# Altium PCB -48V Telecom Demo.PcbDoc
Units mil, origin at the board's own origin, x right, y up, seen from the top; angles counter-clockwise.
Board outline 3540 x 2330 mil, 2 copper layers (Top Layer, Bottom Layer), stack 62 mil thick; 60 components, 18 nets, 123 pads, 37 vias.
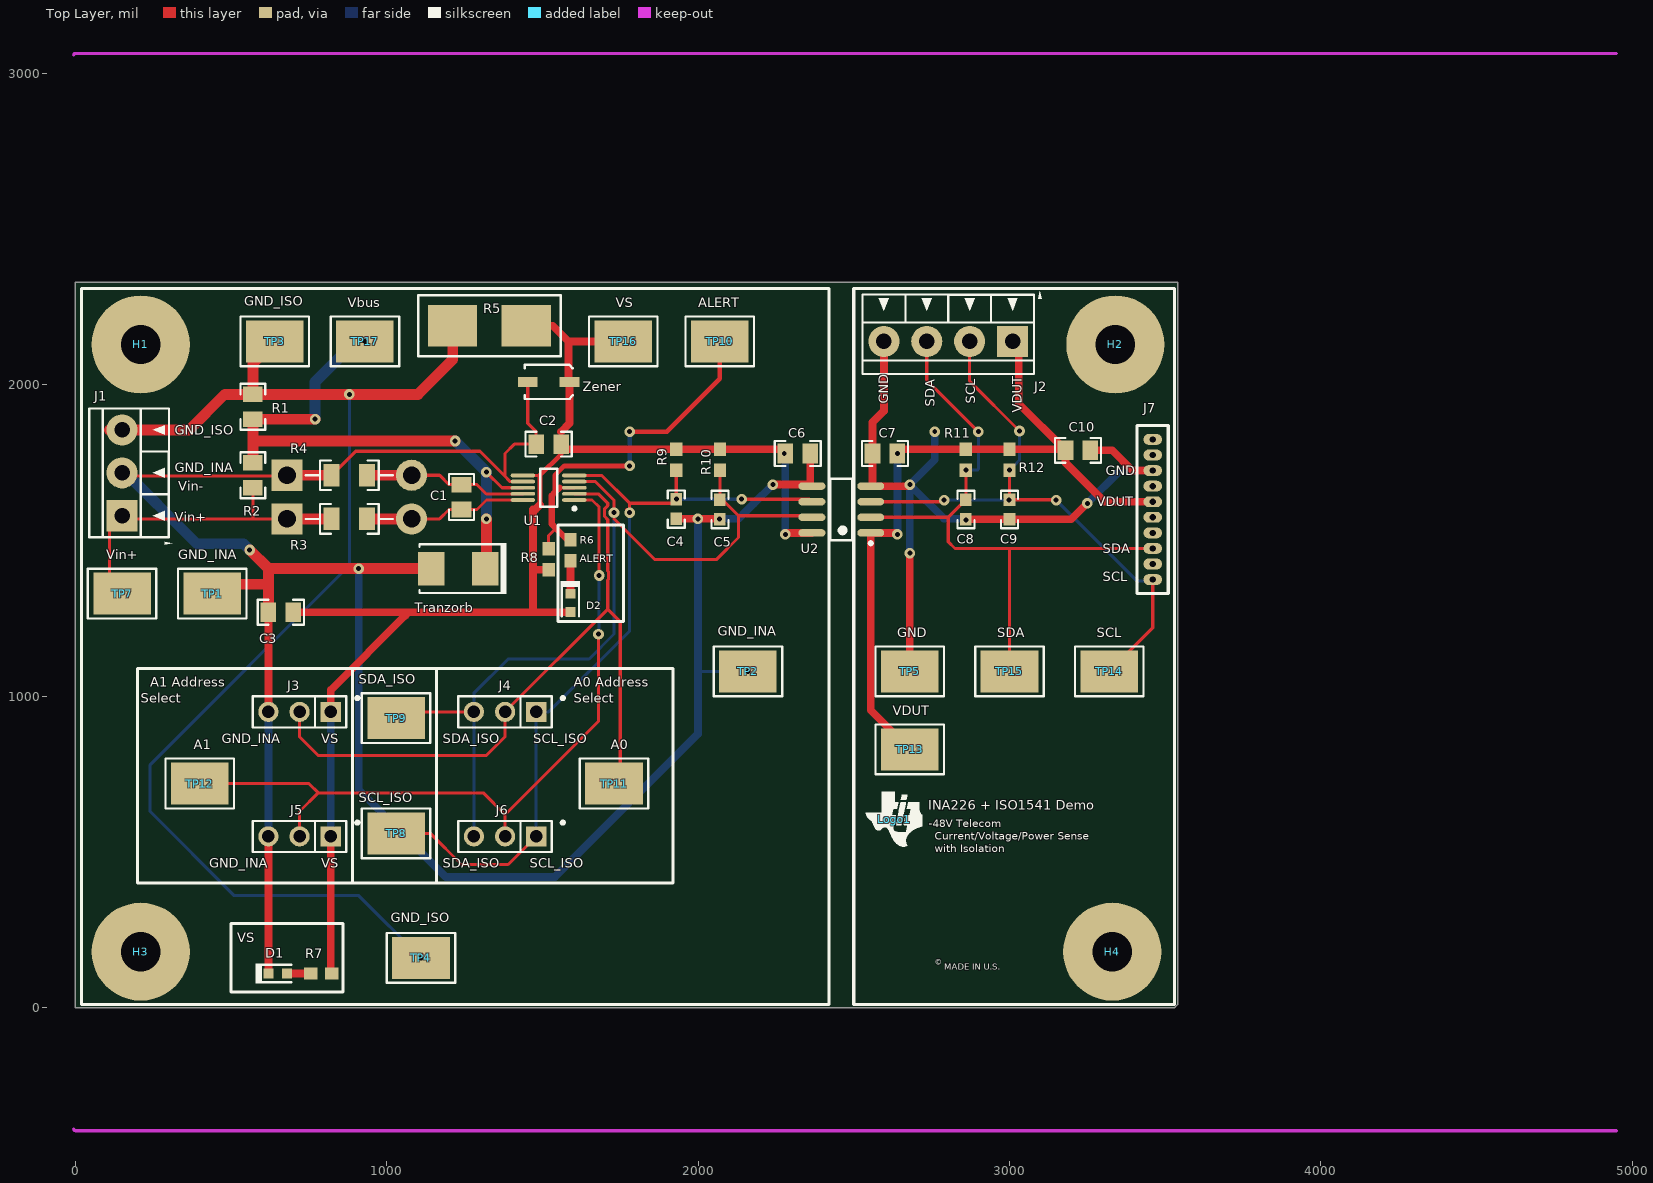
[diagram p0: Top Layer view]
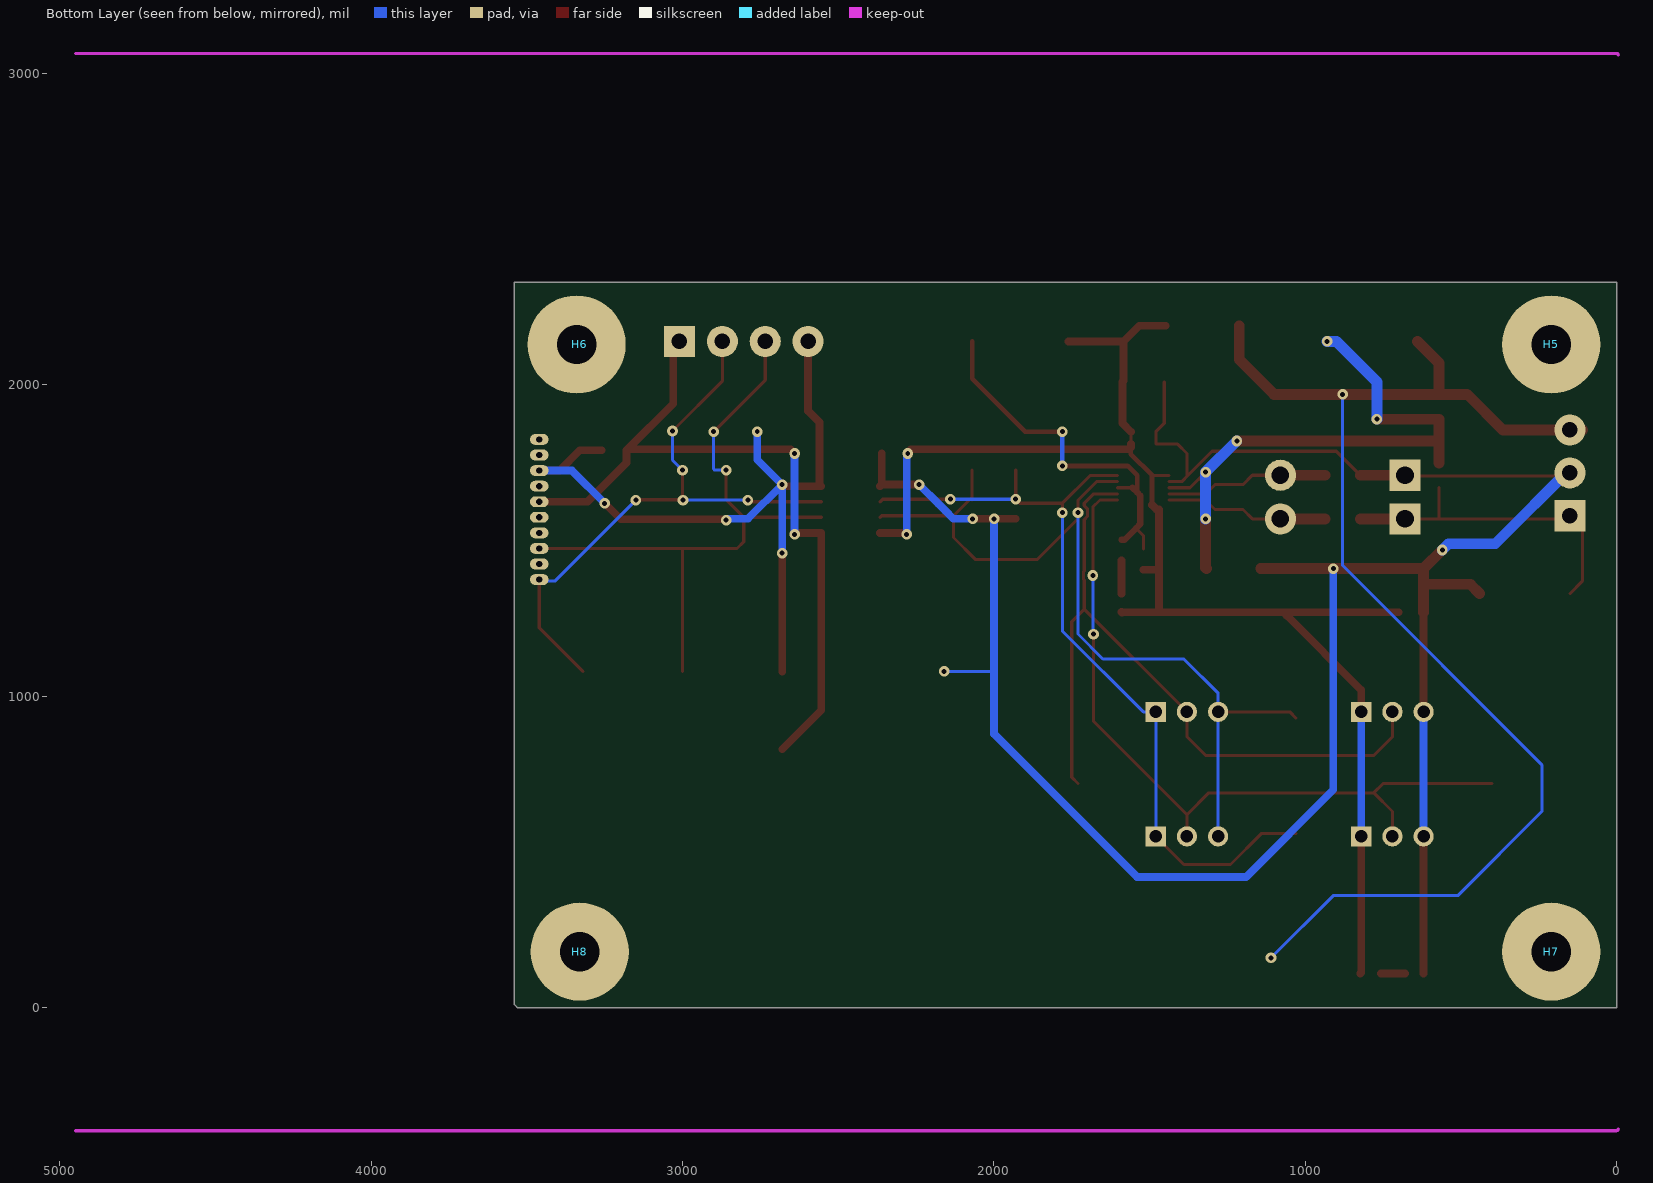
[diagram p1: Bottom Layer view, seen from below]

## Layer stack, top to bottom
Top Layer: signal copper 1.4
Dielectric: core 59.2, FR-4, Dk 4.8
Bottom Layer: signal copper 1.4

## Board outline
3540,10 3530,0 0,0 0,2330 3540,2330

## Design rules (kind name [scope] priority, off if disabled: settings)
AcuteAngle [All] p1: minimum=4.50000000000000E+0001 checktracksonly=FALSE
AssemblyTestPointUsage [All] p1: valid=2
Clearance Clearance_BoardEdge_MountingHoles [OnCopper and InComponentClass('Mounting Holes') vs IsKeepOut] p1: gap=40
Clearance Clearance_BoardEdge_Poly [OnCopper and InPoly vs IsKeepOut] p2: gap=25
Clearance Clearance_BoardEdge [OnCopper and Not InComponentClass('Logo') and not InComponentClass('FiducialMark') and not InRegion(1000,500,4000,800) and Not IsKeepout vs IsKeepOut] p3: gap=75
Clearance Clearance_Poly [InPolygon] p4: gap=25
Clearance [All] p5: gap=7
ComponentClearance ComponentClearance_Logo [InComponentClass(Logo)] p1: gap=50 collisioncheckmode=3 verticalgap=10 showdistances=FALSE
ComponentClearance ComponentClearance_ScrewToNut [(HasFootprint('NY PMS 440 0025 PH')) vs (HasFootprint('Keystone_1902C'))] p2: gap=5 collisioncheckmode=3 verticalgap=10 showdistances=FALSE
ComponentClearance ComponentClearance_MountingHoles [InComponentClass('Mounting Holes')] p3: gap=60 collisioncheckmode=3 verticalgap=100000 showdistances=TRUE
ComponentClearance ComponentClearance_SmallPassives [HasFootprint('0201*') or HasFootprint('0402*') or HasFootprint('0508') or HasFootprint('0603*') or HasFootprint('0612') or HasFootprint('0805*') or HasFootprint('0815*') or HasFootprint('0830*') or HasFootprint('1206*') or HasFootprint('1210*') or HasFootprint('1808*') or HasFootprint('1812*') or HasFootprint('1825*') or HasFootprint('2010*') or HasFootprint('2220*') or HasFootprint('2225*') or HasFootprint('2512*') or HasFootprint('2728*') or HasFootprint('3518*') vs HasFootprint('0201*') or HasFootprint('0402*') or HasFootprint('0508') or HasFootprint('0603*') or HasFootprint('0612') or HasFootprint('0805*') or HasFootprint('0815*') or HasFootprint('0830*') or HasFootprint('1206*') or HasFootprint('1210*') or HasFootprint('1808*') or HasFootprint('1812*') or HasFootprint('1825*') or HasFootprint('2010*') or HasFootprint('2220*') or HasFootprint('2225*') or HasFootprint('2512*') or HasFootprint('2728*') or HasFootprint('3518*')] p4: gap=20 collisioncheckmode=3 verticalgap=10 showdistances=FALSE
ComponentClearance ComponentClearance_THtoSMT [IsThruComponent vs IsSMTComponent] p5: gap=60 collisioncheckmode=3 verticalgap=100000 showdistances=FALSE
ComponentClearance ComponentClearance_THtoTH [IsThruComponent vs IsThruComponent] p6: gap=60 collisioncheckmode=3 verticalgap=100000 showdistances=FALSE
ComponentClearance [All] p7: gap=40 collisioncheckmode=3 verticalgap=10 showdistances=FALSE
DiffPairsRouting [All] p1: maxlimit=100 minlimit=10 mostfreqgap=10 maxuncoupledlength=1000
FabricationTestPointUsage TestPointUsage [All] p1: valid=2 allowmultiple=FALSE
FabricationTestpoint Testpoint [All] p1: side=3 testpointundercomponent=TRUE minsize=40 maxsize=100 preferedsize=60 minholesize=0 maxholesize=40 preferedholesize=32 testpointgrid=1 allowsidetop=TRUE allowsidebottom=TRUE usegrid=TRUE gridtolerance=0.01
FanoutControl Fanout_LCC [IsLCC] p1: bgadir=Out bgaviamode=Centered fanoutstyle=Auto fanoutdirection=Alternating viagrid=1 // Fanout_LCC (Default Rule)
FanoutControl Fanout_BGA [IsBGA] p2: bgadir=Out bgaviamode=Centered fanoutstyle=Auto fanoutdirection=Alternating viagrid=1 // Fanout_BGA (Default Rule)
FanoutControl Fanout_Default [All] p4: bgadir=Out bgaviamode=Centered fanoutstyle=Auto fanoutdirection=Alternating viagrid=1 // Fanout_Default (Default Rule)
FanoutControl Fanout_Small [(CompPinCount < 5)] p5: bgadir=Out bgaviamode=Centered fanoutstyle=Auto fanoutdirection=OutThenIn viagrid=1 // Fanout_Small (Default Rule)
HoleSize [All] p1: absolutevalues=TRUE maxlimit=251 minlimit=8 maxpercent=80.000 minpercent=20.000
MinimumAnnularRing [All] p1: minimumring=7
MinimumSolderMaskSliver MinimumSolderMaskSliver_Logo [InComponentClass('Logo') vs InComponentClass('Logo')] p1: minsoldermaskwidth=0.7
MinimumSolderMaskSliver [All] p2: minsoldermaskwidth=4
PlaneConnect [All] p1: planeconnectstyle=Relief reliefexpansion=10 reliefentries=4 reliefconductorwidth=10 reliefairgap=10
PolygonConnect [All] p1: connectstyle=Relief reliefconductorwidth=10 reliefentries=4 polygonreliefangle="90 Angle" airgapwidth=10
RoutingVias [All] p1: holewidth=16 width=34 viastyle="Through Hole" minholewidth=8 minwidth=26 maxholewidth=40 maxwidth=65
SMDToCorner [All] p1: distance=30000
SilkToSilkClearance [All] p1: silktosilkclearance=5
SilkscreenOverComponentPads [All] p1: minsilkscreentomaskgap=5
SolderMaskExpansion [All] p1: expansion=3
Width [All] p1: maxlimit=100 minlimit=6 preferedwidth=10 checkconnectedcopper=TRUE
14 further rules are at their usual default settings.

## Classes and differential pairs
component class "-48V Telecom Demo_Hardware": H1 H2 H3 H4 H5 H6 H7 H8 Logo1
component class Logo: Logo1
component class "Mounting Holes": H1 H2 H3 H4
component class "-48V Telecom Demo_Main": C1 C2 C3 C4 C5 C6 C7 C8 C9 C10 D1 D2 D3 J1 J2 J3 J4 J5 J6 J7 R1 R2 R3 R4 R5 R6 R7 R8 R9 R10 R11 R12 TP1 TP2 TP3 TP4 TP5 TP7 TP8 TP9 TP10 TP11 TP12 TP13 TP14 TP15 TP16 TP17 Tranzorb U1 U2 Zener
component class Header: J3 J4 J5 J6

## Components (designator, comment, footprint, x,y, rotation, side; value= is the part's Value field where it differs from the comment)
C1 "08055C104KAT2A" 0805_HV 1240,1640 r270 top
C2 "08055C104KAT2A" 0805_HV 1520,1810 r0 top
C3 "C2012X5R1E106K125AB" 0805_HV 660,1270 r180 top
C4 "06031A330JAT2A" 0603 1930,1601.5 r270 top
C5 "06031A330JAT2A" 0603 2070,1600 r270 top
C6 "08055C104KAT2A" 0805_HV 2320,1780 r0 top
C7 "08055C104KAT2A" 0805_HV 2600,1780 r180 top
C8 "06031A330JAT2A" 0603 2860,1600 r270 top
C9 "06031A330JAT2A" 0603 3000,1600 r270 top
C10 "C2012X5R1E106K125AB" 0805_HV 3220,1790 r0 top
D1 "LTST-C190GKT" LED_LTST-C190 650,110 r180 top
D2 "LTST-C190CKT" LED_LTST-C190_Red 1590,1300 r90 top
H1 "NY PMS 440 0025 PH" "NY PMS 440 0025 PH"#1 210,2130 r0 top locked
H2 "NY PMS 440 0025 PH" "NY PMS 440 0025 PH"#2 3330,2130 r0 top locked
H3 "NY PMS 440 0025 PH" "NY PMS 440 0025 PH"#1 210,180 r0 top locked
H4 "NY PMS 440 0025 PH" "NY PMS 440 0025 PH"#1 3330,180 r0 top locked
H5 "1902C" Keystone_1902C 210,2130 r180 bottom locked
H6 "1902C" Keystone_1902C 3330,2130 r180 bottom locked
H7 "1902C" Keystone_1902C 210,180 r180 bottom locked
H8 "1902C" Keystone_1902C 3330,180 r180 bottom locked
J1 "ED555/3DS" TERM_BLK_ED555-3DS 150,1580 r90 top
J2 "ED555/4DS" TERM_BLK_ED555-4DS 3010,2140 r180 top
J3 "TSW-103-07-G-S" TSW-103-07-G-S 720,950 r180 top
J4 "TSW-103-07-G-S" TSW-103-07-G-S 1380,950 r180 top
J5 "TSW-103-07-G-S" TSW-103-07-G-S 720,550 r180 top
J6 "TSW-103-07-G-S" TSW-103-07-G-S 1380,550 r180 top
J7 "851-43-010-20-001000" 851-43-010-20-001000 3460,1600 r180 top
Logo1 "Texas Instruments" TI_Symbol_Overlay_Small 2629.34,605.46 r0 top
R1 "CRCW080535K7FKEA" 0805_HV 570,1930 r90 top
R2 "CRCW080512K1FKEA" 0805_HV 570,1710 r90 top
R3 "ax1206-1" ax1206 880,1570 r0 top
R4 "ax1206-1" ax1206 880,1710 r0 top
R5 "1.80k" Resistor_4122 1330,2190 r180 top
R6 "910" 3-0603 1590,1469.53 r90 top
R7 "910" 3-0603 790,110 r0 top
R8 "10k" 3-0603 1520,1440 r90 top
R9 "10k" 3-0603 1930,1760 r90 top
R10 "10k" 3-0603 2070,1760 r90 top
R11 "10k" 3-0603 2860,1760 r90 top
R12 "10k" 3-0603 3000,1760 r90 top
TP1 "GND_INA" Testpoint_Keystone_Compact 440,1330 r0 top
TP2 "GND_INA" Testpoint_Keystone_Compact 2160,1080 r0 top
TP3 "GND_ISO" Testpoint_Keystone_Compact 640,2140 r0 top
TP4 "GND_ISO" Testpoint_Keystone_Compact 1110,160 r0 top
TP5 "GND" Testpoint_Keystone_Compact 2680,1080.13 r0 top
TP7 "Vin+" Testpoint_Keystone_Compact 150,1330 r0 top
TP8 "SCL_ISO" Testpoint_Keystone_Compact 1030,560 r0 top
TP9 "SDA_ISO" Testpoint_Keystone_Compact 1030,930 r0 top
TP10 "ALERT" Testpoint_Keystone_Compact 2070,2140 r0 top
TP11 "A0" Testpoint_Keystone_Compact 1730,720 r0 top
TP12 "A1" Testpoint_Keystone_Compact 400,720 r0 top
TP13 "VDUT" Testpoint_Keystone_Compact 2680,830 r0 top
TP14 "SCL" Testpoint_Keystone_Compact 3320,1080.13 r0 top
TP15 "SDA" Testpoint_Keystone_Compact 3000,1080.13 r0 top
TP16 "VS" Testpoint_Keystone_Compact 1760,2140 r0 top
TP17 "Vbus" Testpoint_Keystone_Compact 930,2140 r0 top
Tranzorb "SMBJ30A-13-F" SMB 1230,1410 r180 top
U1 "INA226" DGS0010A_M 1520,1670 r180 top
U2 "ISO1541" D0008A_N 2460,1600 r180 top
Zener "4.7V" SOD-123 1520,2010 r0 top

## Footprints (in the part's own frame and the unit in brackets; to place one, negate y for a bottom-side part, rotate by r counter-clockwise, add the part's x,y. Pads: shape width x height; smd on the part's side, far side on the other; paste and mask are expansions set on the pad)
3-0603 [mm] "Chip Resistor; Body 1.6 x 0.9 mm (LxW typ)"
  rect 1.1x1 smd: 1(-0.85,0) 2(0.85,0)
0603 [mm] "0603 from SM-752 data"
  rect 1x0.95 smd: 1(-0.8,0) 2(0.8,0)
  silkscreen extent -1.52,-0.69 1.52,0.69, body extent -0.87,-0.47 0.87,0.47, height 0.85
0805_HV [mil] "0805 with 30mil clearance between pads"
  rect 50x63 smd: 1(-40,0) 2(40,0)
  silkscreen extent -74,-40 74,40, body extent -43,-29 43,29, height 43
851-43-010-20-001000 [mil] "Female 10 Pin connector for SM-USB-DIG"
  oval 60x35 hole 20: 1(0,225) 2(0,175) 3(0,125) 4(0,75) 5(0,25) 6(0,-25) 7(0,-75) 8(0,-125) 9(0,-175) 10(0,-225)
  silkscreen extent -50,-270 50,270, body extent -210,-257 8,257, height 87
ax1206 [mm]
  rect 2.54x2.54 hole 1.448: 1(-5.08,0)
  rect 1.3x1.85 smd: 1(-1.45,0) 2(1.45,0)
  round 2.54 hole 1.448: 2(5.08,0)
  Top Layer lines w0.889: -5.08,0 -1.45,0 ; 1.45,0 5.08,0
  silkscreen extent -3.55,-1.21 3.55,1.21, body extent -5.42,-1.01 5.42,1.02, height 3.55
D0008A_N [mm] "SOIC, 8-Leads, Body 4.9x3.9mm, Pitch 1.27mm, IPC Medium Density"
  oval 2.2x0.6 smd: 1(-2.4,1.905) 2(-2.4,0.635) 3(-2.4,-0.635) 4(-2.4,-1.905) 5(2.4,-1.905) 6(2.4,-0.635) 7(2.4,0.635) 8(2.4,1.905)
  silkscreen extent -2.53,-2.5 0.9,2.88, body extent -2,-2.5 2,2.5, height 1.75
DGS0010A_M [mm] "TSSOP, 10-Leads, Body 3x3mm, Pitch 0.5mm, IPC Low Density"
  oval 2x0.3 smd: 1(-2.1,1) 2(-2.1,0.5) 3(-2.1,0) 4(-2.1,-0.5) 5(-2.1,-1) 6(2.1,-1) 7(2.1,-0.5) 8(2.1,0) 9(2.1,0.5) 10(2.1,1)
  silkscreen extent -2.22,-1.55 0.7,1.82, body extent -1.55,-1.55 1.55,1.55, height 1.1
Keystone_1902C [mil] "Hex Standoff, 4-40 threaded, nylon"
  body extent -145,-126 146,126, height 501
LED_LTST-C190 [mm] "Lite-On"
  rect 0.8x0.8 smd: 1(-0.75,0) 2(0.75,0)
  silkscreen extent -1.1,-0.8 1.8,0.8, body extent -0.85,-0.45 0.85,0.45, height 0.9
LED_LTST-C190_Red [mm] "Lite-On"
  rect 0.8x0.8 smd: 1(-0.75,0) 2(0.75,0)
  silkscreen extent -1.1,-0.8 1.8,0.8, body extent -0.85,-0.45 0.85,0.45, height 0.9
"NY PMS 440 0025 PH"#1 [mm] "4-40 nylon screw and mounting hole"
  round 8 hole 3.2: 1(0,0)
  body extent -3.3,-3.3 3.3,3.3, height 2.69
"NY PMS 440 0025 PH"#2 [mm] "4-40 nylon screw and mounting hole"
  round 8 hole 3.2: 1(0.254,0)
  body extent -3.3,-3.3 3.3,3.3, height 2.69
Resistor_4122 [mm]
  rect 4x3.4 smd: 1(-3,0) 2(3,0)
  silkscreen extent -5.8,-2.5 5.8,2.5
SMB [mil] "Molded Diode, 2-Leads, Body 5.4x3.6mm, IPC Medium Density, based on OnSemi component dimensions"
  rect 85x107.99 smd: 1(-87.01,0) 2(87.01,0)
  silkscreen extent -155,-82 125,82, body extent -106,-71 106,71, height 91
SOD-123 [mm] "SOD-123; 2 Leads; Body 2.7 x 1.6 mm, (LxW)"
  rect 1.6x0.8 smd: 1(-1.7,0) 2(1.7,0)
  silkscreen extent -1.95,-1.4 1.95,1.4
TERM_BLK_ED555-3DS [mm]
  rect 2.54x2.54 hole 1.27: 1(0,0)
  round 2.54 hole 1.27: 2(3.5,0) 3(7,0)
  silkscreen extent -2.36,-4.09 8.75,2.67, body extent -1.75,-3.83 8.75,2.67, height 8.2
TERM_BLK_ED555-4DS [mm]
  rect 2.54x2.54 hole 1.27: 1(0,0)
  round 2.54 hole 1.27: 2(3.5,0) 3(7,0) 4(10.5,0)
  silkscreen extent -2.36,-4.09 12.25,2.67, body extent -1.75,-3.8 12.25,2.7, height 8.2
Testpoint_Keystone_Compact [mil] "Compact SMT test point"
  rect 185x135 smd: 1(0,0)
  silkscreen extent -110,-80 110,80, body extent -75,-56 75,56, height 91
TI_Symbol_Overlay_Small [mil]
  silkscreen extent -90,-88 91,88
TSW-103-07-G-S [mm] "Samtec 100mil, 1x3, 230 mil above insulator"
  rect 1.65x1.65 hole 1.016 mask+0: 1(-2.54,0)
  round 1.65 hole 1.016 mask+0: 2(0,0) 3(2.54,0)
  silkscreen extent -4.84,-1.27 3.81,1.27, body extent -3.81,-1.27 3.81,1.27, height 8.38

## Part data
C1 C2 C6 C7: "CAP, CERM, 0.1uF, 50V, +/-10%, X7R, 0805"
C3 C10: "CAP, CERM, 10uF, 25V, +/-10%, X5R, 0805"
C4 C5 C8 C9: "CAP, CERM, 33pF, 100V, +/-5%, C0G/NP0, 0603"
D1: "LED, Green, SMD"
D2: "LED, Red, SMD"
H1 H2 H3 H4: "Machine Screw, Round, #4-40 x 1/4, Nylon, Philips panhead"
H5 H6 H7 H8: "Standoff, Hex, 0.5\"L #4-40 Nylon"
J1: "Terminal Block, 6A, 3.5mm Pitch, 3-Pos, TH"
J2: "Terminal Block, 6A, 3.5mm Pitch, 4-Pos, TH"
J3 J4 J5 J6: "Header, TH, 100mil, 3x1, Gold plated, 230 mil above insulator"
J7: library part SM-USB-DIG-CONN, "10-Pin 50-mil Connector of SM-USB-DIG"
Logo1: library part TI_Logo, "Texas Instrument Corporate Signature"
R1: "RES, 35.7k ohm, 1%, 0.125W, 0805"
R2: "RES, 12.1k ohm, 1%, 0.125W, 0805"
R3 R4: library part ax1206-2, "RES, 1.00k ohm, 1%, 0.25W, 1206+axial"
R5: library part Resistor_4122
R6 R7 R8 R9 R10 R11 R12: library part ERJ3GE, "Thick Film Chip Resistor, 1 Ohm to 10M Ohm Range, 5% Tolerance, 0603 Size, 0.1 W"
TP1 TP2 TP3 TP4 TP5 TP7 TP8 TP9 TP10 TP11 TP12 TP13 TP14 TP15 TP16 TP17: library part 5016, "Test Point, Compact, SMT"
Tranzorb: library part SMBJ24A-13-F, "Diode, TVS, Uni, 24V, 600W, SMB"
Zener: library part BZT52C4V7, "Surface Mount Zener Diode"

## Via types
v1: diameter 34, hole 16, Top Layer to Bottom Layer, 37 vias

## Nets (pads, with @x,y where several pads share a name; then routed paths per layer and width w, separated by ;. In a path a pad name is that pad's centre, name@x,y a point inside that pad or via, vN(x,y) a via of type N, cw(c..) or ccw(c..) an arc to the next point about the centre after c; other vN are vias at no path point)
A0: J3.2 J4.2 TP11.1 U1.2 | length 2391.1
  Top Layer w10: J3.2 720,870 780,810 1320,810 1380,870 J4.2 1710,1280 ; U1.2 1679.68,1650.32 1710,1620 1710,1612.43 1700,1602.43 1700,1577.57 1710,1567.57 1710,1402.43 1712,1400.43 1712,1375.57 1710,1373.57 1710,1280 ; TP11.1 1750,740 1750,1240 1710,1280
A1: J5.2 J6.2 TP12.1 U1.1 | length 2464.1
  Top Layer w10: TP12.1 750,720 780,690 ; J5.2 720,630 780,690 ; J6.2 1380,620 ; U1.1 1659.37,1630.63 1682,1608 v1(1682,1388) v1@1682,1382 ; v1(1680,1200) 1680,920 1380,620 ; 780,690 1310,690 1380,620
  Bottom Layer w10: v1(1680,1200) 1682,1202 v1(1682,1388)
ALERT: R6.2 R8.2 TP10.1 U1.3 | length 1225
  Top Layer w10: R8.2 1520,1516.54 1543.46,1540 ; 1560,1670 U1.3
  Top Layer w15: 1540,1654.91 1540,1710 1547.81,1717.81 1547.81,1718.24 1560.35,1730.78 1560.78,1730.78 1570,1740 v1(1780,1740) ; v1(1780,1850) 1900,1850 2070,2020 TP10.1
  Top Layer w20: 1555.09,1670 1540,1654.91 1530,1644.91 1530,1553.47 1543.46,1540 1580.47,1503 R6.2
  Bottom Layer w15: v1(1780,1740) v1(1780,1850)
GND: C7.2 C8.2 C9.2 C10.2 J2.4 J7.8 TP5.1 U2.4 | length 2528.8
  Top Layer w25: J2.4 2596.61,1916.61 2560,1880 C7.2 2560,1680.51 U2.4 2675,1675 v1(2680,1680) ; TP5.1 v1(2680,1460) ; C8.2 C9.2 3198.5,1568.5 v1(3250,1620) ; C10.2 3330,1790 3395,1725 J7.8
  Bottom Layer w25: v1(2680,1460) v1(2680,1680) ; v1(2760,1850) 2760,1760 v1(2680,1680) ; v1@2858.5,1570 2790,1570 v1(2680,1680) ; v1(3250,1620) 3355,1725 J7.8
  other v1: 2860,1565.55
GND_INA: C2.1 C3.2 C4.2 C5.2 C6.2 D1.2 J1.2 J3.3 J5.3 R4.1 TP1.1 TP2.1 Tranzorb.2 U1.7 U2.5 Zener.1 | length 7828.6
  Top Layer w10: J1.2@110,1717.8 120,1707.8 677.8,1707.8 R4.1@680,1710 ; R4.1@822.91,1710 900,1787.09 1299.41,1787.09 1377.38,1709.11 ; U1.7 1396.81,1689.69 1377.38,1709.11 ; Zener.1 1453.07,1876.93 1480,1850 C2.1 1410,1810 1380,1780 1380,1711.73 1377.38,1709.11
  Top Layer w25: J5.3 620,110.47 D1.2 ; J3.3 C3.2 ; C4.2 v1(1999.25,1570) v1(2068.5,1570) C5.2 ; v1(2240,1680) 2359.49,1680 U2.5@2360,1680.51 ; C6.2 U2.5@2360,1680.51 ; U2.5 U2.5@2360,1680.51
  Top Layer w35: TP1.1 470,1360 620,1360 ; v1(560,1470) 620,1410 ; C3.2 620,1360 ; Tranzorb.2 v1(910,1410) 620,1410 ; 620,1360 620,1410
  Bottom Layer w10: 1999.25,1080 v1(2160,1080)
  Bottom Layer w25: J5.3 J3.3 ; v1(910,1410) 910,700 1190,420 1540,420 1999.25,879.25 1999.25,1080 v1(1999.25,1570) ; v1(2068.5,1570) 2130,1570 2155.49,1595.49 ; 2155.53,1595.49 2177.5,1617.46 ; 2177.5,1617.5 v1(2240,1680)
  Bottom Layer w35: J1.2@142.21,1737.79 390,1490 540,1490 v1(560,1470)
GND_ISO: J1.3 R1.2 R5.2 TP3.1 TP4.1 | length 4172.5
  Top Layer w35: J1.3@110,1855.59 365.59,1855.59 480,1970 R1.2 ; TP3.1 570,2070 R1.2 ; R5.2 1211.89,2081.89 1100,1970 v1(880,1970) R1.2
  Bottom Layer w10: v1(880,1970) 880,1420 240,780 240,630 510,360 910,360 v1(1110,160)
NetC1_1: C1.1 R4.2 U1.9 | length 382.3
  Top Layer w10: R4.2@1080,1710 1170,1710 1200,1680 C1.1 1290,1680 1320,1650 1437.01,1650 U1.9
NetC1_2: C1.2 R3.2 U1.10 | length 382.4
  Top Layer w10: R3.2@1080,1570 1170,1570 1200,1600 C1.2 1290,1600 1320.63,1630.63 U1.10
NetD1_1: D1.1 R7.1 | length 77
  Top Layer w25: D1.1 R7.1
NetD2_2: D2.2 R6.1 | length 106.5
  Top Layer w25: D2.2 R6.1
SCL: C9.1 J2.2 J7.1 R12.1 TP14.1 U2.3 | length 1957.4
  Top Layer w10: U2.3 2785,1625 v1(2790,1630) ; J2.2 2872.2,2012.21 v1(3032.2,1852.21) ; v1(3000,1726.54) C9.1 3148.5,1631.5 v1(3150,1630) ; TP14.1 3460,1220.13 J7.1
  Bottom Layer w10: v1(2790,1630) v1(2998.5,1630) ; v1(3000,1726.54) 3032.2,1758.74 v1(3032.2,1852.21) ; v1(3150,1630) 3410,1370 3455,1370 J7.1
SCL_ISO: C4.1 J4.1 J6.1 R9.1 TP8.1 U1.5 U2.6 | length 2652
  Top Layer w10: TP8.1 1140,560 1240,460 1390,460 J6.1 ; U1.5 1690.63,1709.37 1780,1620 ; v1@1770,1600 v1(1780,1590) ; v1@1780,1601.26 1780,1620 ; R9.1 v1(1930,1632.99) 1917.01,1620 1780,1620 ; v1(2140,1632.99) 2357.52,1632.99 U2.6
  Bottom Layer w10: J6.1 J4.1 1520,950 1780,1210 v1(1780,1590) ; v1(1930,1632.99) v1@2137.01,1632.99 ; v1@2138.5,1630 2140,1630 v1@2138.5,1631.5
SDA: C8.1 J2.3 J7.3 R11.1 TP15.1 U2.2 | length 2082.7
  Top Layer w10: U2.2 2803.5,1575 ; J2.3 2734.41,2015.59 v1(2900,1850) ; v1(2860,1726.54) C8.1 2803.5,1575 ; TP15.1 3000,1475 ; J7.3 3000,1475 ; 2803.5,1575 2803.5,1496.5 2825,1475 3000,1475
  Bottom Layer w10: v1(2860,1726.54) 2896.54,1726.54 2900,1730 v1(2900,1850)
SDA_ISO: C5.1 J4.3 J6.3 R10.1 TP9.1 U1.4 U2.7 | length 2819.6
  Top Layer w10: TP9.1 1050,950 J4.3 ; U1.4 1669.69,1689.69 1670,1690 1730,1630 v1(1730,1590) 1730,1570 1860,1440 2060,1440 2130,1510 2130,1580 ; C5.1 C5.1@2070,1640 ; R10.1 C5.1@2070,1640 ; U2.7 2360.51,1580 2130,1580 ; C5.1@2070,1640 2130,1580
  Bottom Layer w10: J6.3 J4.3 1280,1010 1390,1120 1650,1120 1730,1200 v1(1730,1590)
VBUS: R1.1 R2.2 TP17.1 Tranzorb.1 U1.8 | length 1911.3
  Top Layer w10: v1(1320,1720) 1370,1670 U1.8
  Top Layer w35: R2.2 570,1820 ; R1.1@570,1886.71 570,1820 ; R1.1 v1(770,1890) ; v1(1220,1820) 570,1820 ; Tranzorb.1 1320,1412.99 v1(1320,1570)
  Bottom Layer w35: v1(770,1890) 770,2010 900,2140 v1(930,2140) ; v1(1220,1820) v1(1320,1720) v1(1320,1570)
VDUT: C7.1 C10.1 J2.1 J7.6 R11.2 R12.2 TP13.1 U2.1 | length 2428.9
  Top Layer w25: v1(2640,1520) 2635,1525 U2.1 2554.49,955.51 TP13.1 ; v1(2640,1780) 2653.46,1793.47 R11.2 R12.2 C10.1@3176.54,1793.47 ; J2.1 3030,2120 3030,1940 C10.1@3176.54,1793.47 ; J7.6 3305,1625 3180,1750 C10.1 C10.1@3176.54,1793.47
  Bottom Layer w25: v1(2640,1520) v1(2640,1780)
VIN+: J1.1 R2.1 R3.1 TP7.1 | length 940.7
  Top Layer w10: TP7.1 110,1370 110,1580 120,1570 570,1570 ; R2.1 570,1570 ; R3.1@680,1570 570,1570
VS: C2.2 C3.1 C6.1 D2.1 J3.1 J5.1 R5.1 R7.2 R8.1 R9.2 R10.2 TP16.1 U1.6 U2.8 Zener.2 | length 4581.6
  Top Layer w10: U1.6 1491.81,1709.37 ; C2.2 1560,1850 ; Zener.2@1583.46,2013.46 Zener.2
  Top Layer w15: 1491.81,1709.37 1560,1777.56 C2.2@1560,1800 ; 1492.44,1614.88 1492.44,1709.37
  Top Layer w25: C3.1 1060,1270 ; J5.1 820,113.47 R7.2 ; J3.1 820,1020 1060,1260 1060,1270 ; R5.1 1533.47,2190 1583.46,2140 ; 1492.44,1614.88 1477.56,1600 1470,1600 1470,1410 ; R8.1 1473.46,1406.54 1470,1410 ; C2.2 1560,1800 1566.54,1793.47 R9.2 R10.2 2266.54,1793.47 C6.1 ; 1560,1850 1586.93,1876.93 Zener.2 ; D2.1@1579.05,1270 1470,1270 ; Zener.2@1583.46,2013.46 1583.46,2140 ; D2.1@1589.06,1269.53 D2.1 ; TP16.1 1583.46,2140 ; v1(2280,1520) 2285,1525 U2.8 ; 1060,1270 1470,1270 ; 1470,1270 1470,1410
  Bottom Layer w25: J5.1 J3.1 ; v1(2276.69,1780) 2280,1776.69 v1(2280,1520)
pads on no net: H1.1 H2.1 H3.1 H4.1 J7.2 J7.4 J7.5 J7.7 J7.9 J7.10

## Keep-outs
Keep-Out Layer:
  lines w10: 4950,-395 0,-395 ; 4950,3065 0,3065 ; -5,-390 ccw(c0,-390) 0,-395 ; -5,-390 ccw(c0,-390) 0,-395 ; -5,-390 ccw(c0,-390) 0,-395 ; -5,-390 ccw(c0,-390) 0,-395 ; -5,-390 ccw(c0,-390) 0,-395 ; -5,-390 ccw(c0,-390) 0,-395 ; -5,3060 cw(c0,3060) 0,3065 ; -5,3060 cw(c0,3060) 0,3065 ; -5,3060 cw(c0,3060) 0,3065 ; -5,3060 cw(c0,3060) 0,3065 ; -5,3060 cw(c0,3060) 0,3065 ; -5,3060 cw(c0,3060) 0,3065
  text ".Layer_Name" at 577,-1248.49 h30

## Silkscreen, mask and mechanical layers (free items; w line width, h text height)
Top Overlay:
  lines w10: 220,1090 1890,1090 1920,1090 1920,1070 ; 230,1090 200,1090 200,400 1900,400 1920,400 1920,1080 ; 890,400 890,1090 ; 1160,400 1160,1090 ; 2520,10 3510,10 3530,10 3530,2310 3510,2310 2520,2310 ; 2530,10 2500,10 2500,2310 2530,2310 ; 20,10 20,2310 2400,2310 2420,2310 2420,10 2400,10 20,10 ; 500,50 500,270 860,270 860,50 500,50 ; 1550,1240 1760,1240 1760,1550 1560,1550 1550,1550 1550,1240
  text "GND" at 2610,1940 h30 r90
  text "SCL" at 2890,1940 h30 r90
  text "SDA" at 2760,1930 h30 r90
  text "VDUT" at 3040,1910 h30 r90
  text "GND_ISO" at 320,1840 h30
  text "GND_INA" at 320,1720 h30
  text "GND" at 3310,1710 h30
  text "Vin-" at 330,1660 h30
  text "VDUT" at 3280,1610 h30
  text "Vin+" at 320,1560 h30
  text "SDA" at 3300,1460 h30
  text "ALERT" at 1620,1430 h25
  text "SCL" at 3300,1370 h30
  text "A1 Address" at 240,1030 h30
  text "A0 Address" at 1600,1030 h30
  text "Select" at 210,980 h30
  text "Select" at 1600,980 h30
  text "GND_INA" at 470,850 h30
  text "VS" at 790,850 h30
  text "SDA_ISO" at 1180,850 h30
  text "SCL_ISO" at 1470,850 h30
  text "INA226 + ISO1541 Demo" at 2739.34,635.46 h30
  text "-48V Telecom" at 2740,580 h25
  text "Current/Voltage/Power Sense" at 2760,540 h25
  text "with Isolation" at 2760,500 h25
  text "GND_INA" at 430,450 h30
  text "VS" at 790,450 h30
  text "SDA_ISO" at 1180,450 h30
  text "SCL_ISO" at 1460,450 h30
  text "VS" at 520,210 h30
  text "©" at 2760.23,131.98 h30
  text "MADE IN U.S." at 2790.23,121.98 h20
Bottom Paste:
  text ".Layer_Name" at 577,-1248.49 h30
Bottom Solder:
  text ".Layer_Name" at 577,-1248.49 h30
Drill Guide:
  text ".Layer_Name" at 577,-1248.49 h30
M1 Board Outline:
  lines w10: 0,0 0,2330 3540,2330 3540,0 0,0
M2 Board Dimensions:
  lines w10: -220,60 -200,0 ; -220,2270 -200,2330 ; -210,0 -190,0 ; -210,2330 -190,2330 ; -200,884.09 -200,0 ; -200,1445.91 -200,2330 ; -180,60 -200,0 ; -180,2270 -200,2330 ; 0,-210 0,-190 ; 60,-220 0,-200 ; 60,-180 0,-200 ; 1489.09,-200 0,-200 ; 2050.91,-200 3540,-200 ; 3480,-220 3540,-200 ; 3480,-180 3540,-200 ; 3540,-210 3540,-190
  text "2330 (mil)" at -164.01,894.09 h60 r90
  text "3540 (mil)" at 1499.09,-235.99 h60
M5 Assembly Top:
  lines w10: -292,-1320.17 6308,-1320.17 ; -292,-1116.83 6310,-1116.83 ; -292,-913.5 -292,-1523.5 3713,-1523.5 6310,-1523.5 6310,-913.5 -291.5,-913.5 -291.5,-1523.5 1284,-1523.5 ; 2173,-1523.5 2173,-913.5 ; 3440,-1116.83 3440,-913.5 ; 4280,-1116.83 4280,-913.5 ; 4902,-1530 4902,-1327.17
  text "COMPONENTS MARKED 'DNP' SHOULD NOT BE POPULATED." at 1153.5,-708.5 h30
  text "ASSEMBLY VARIANT:" at 1153,-824 h30
  text ".VariantName" at 2189,-824 h30
  text "PCB VIEWED FROM TOP SIDE" at -228.5,-1045.67 h30
  text "BOARD #:" at 2248,-1045.67 h30
  text ".PRJ_Number" at 2793.5,-1045.67 h30
  text "REV:" at 3638,-1045.67 h30
  text ".PCB_Rev" at 3929.5,-1045.67 h30
  text "SVN REV:" at 4476,-1045.67 h30
  text ".VersionControl_RevNumber" at 4982,-1045.67 h30
  text "IGNORE ->" at -228.5,-1248.49 h30
  text "PLOT NAME =" at -228.5,-1454.34 h30
  text ".plot_File_Name" at 577,-1454.34 h30
  text "GENERATED    :" at 2250,-1454.34 h30
  text ".Print_Date" at 3119.5,-1454.34 h30
  text ".Print_Time" at 3848.5,-1454.34 h30
  text "TEXAS INSTRUMENTS" at 5113,-1454.34 h30
M9 Title Sheet:
  drawing of 57 lines, arcs and shapes, not listed
  text "1" at 739.84,7646.5 h70
  text "2" at 3235.5,7646.5 h70
  text "3" at 5724.84,7646.5 h70
  text "4" at 8231.51,7646.5 h70
  text "5" at 10730.5,7646.5 h70
  text "6" at 13235.5,7646.5 h70
  text "A" at -416.5,6503.5 h70
  text "A" at 14383.5,6503.5 h70
  text "B" at -416.5,4123.5 h70
  text "B" at 14383.5,4123.5 h70
  text "C" at -416.5,1748.5 h70
  text "C" at 14383.5,1748.5 h70
  text "PROJECT TITLE:" at 11343.5,-112.5 h45
  text ".PRJ_Title" at 11393.5,-245.83 h70
  text "DESIGNED FOR:" at 11343.5,-413.5 h45
  text ".PRJ_Customer" at 11393.5,-553.5 h70
  text "D" at -416.5,-621.5 h70
  text "D" at 14383.5,-621.5 h70
  text "FILE NAME:" at 11343.5,-713.5 h45
  text ".PCB_File_Name_No_Path" at 11393.5,-833.5 h70
  text "Texas Instruments (TI) and/or its licensors do not warrant the accuracy or completeness of this specification" at 6374,-995.34 h45
  text "ENGINEER:" at 11343.5,-1003.5 h45
  text "LAYOUT BY:" at 12848.5,-1003.5 h45
  text "or any information contained therein. TI and/or its licensors do not warrant that this design will meet" at 6329.01,-1108 h45
  text ".PRJ_Engineer" at 11393.5,-1158.49 h70
  text ".PCB_Layout" at 12899,-1158.49 h70
  text "the specifications, will be suitable for your application or fit for any particular purpose, or will operate in" at 6329.01,-1220.67 h45
  text ".Layer_Name" at 577,-1248.49 h60
  text "ALTIUM DESIGNER VERSION:" at 12848.5,-1313.5 h45
  text "an implementation. TI and/or its licensors do not warrant that the design is production worthy. You should" at 6329.01,-1333.33 h45
  text "completely validate and test your design implementation to confirm the system functionality for your application." at 6374,-1446 h45
  text ".print_Scale" at 11393.5,-1446.83 h70
  text ".Application_BuildNumber" at 12899,-1446.83 h70
  text "1" at 739.84,-1653.5 h70
  text "2" at 3235.5,-1653.5 h70
  text "3" at 5724.84,-1653.5 h70
  text "4" at 8231.51,-1653.5 h70
  text "5" at 10730.5,-1653.5 h70
  text "6" at 13235.5,-1653.5 h70
M10 Fab Notes:
  drawing of 187 lines, arcs and shapes, not listed
  text "DESIGN INFORMATION" at 5051.02,5530 h30
  text "(REFER ALSO ARRAY/PANEL PROFILING INFORMATION)" at 4689.46,5368.29 h30
  text "BOARD SIZE" at 4003.46,5364 h30
  text "3540MIL" at 4465.78,5236.18 h30
  text "X" at 4971.46,5236.18 h30
  text "2330MIL" at 5202.78,5236.18 h30
  text "Number of Layers :" at 4406.46,5039 h30
  text "2" at 5501.27,5029 h30
  text "MIN. TRACK WIDTH:" at 4406.46,4900 h30
  text "8" at 5502.7,4900 h30
  text "MIL" at 5657.46,4900 h30
  text "MIN. CLEARANCE:" at 4406.46,4768 h30
  text "8" at 5502.7,4768 h30
  text "MIL" at 5657.46,4768 h30
  text "MIN. VIA PAD SIZE:" at 4406.46,4636 h30
  text "24" at 5472.71,4636 h30
  text "MIL" at 5657.46,4636 h30
  text "0.05mm (2MIL)" at 5101.46,4494.29 h30
  text "MINIMUM ANNULAR RING" at 4077.23,4490 h30
  text "EXTERNAL" at 5809.46,4490 h30
  text "PER" at 4277.23,4372 h30
  text "IPC-D-275 CLASS 2 LEVEL C" at 4497.23,4372 h30
  text "MIL, HOLES" at 5985.46,4259.71 h30
  text "+/-" at 5593,4259 h30
  text "+/-" at 6447,4259 h30
  text "REGISTRATION TOLERANCES:" at 4077.23,4254 h30
  text "METAL" at 5277,4254 h30
  text "5" at 5853.2,4254 h30
  text "3" at 6686.2,4254 h30
  text "MIL" at 6802.46,4254 h30
  text "MATERIAL:" at 4002.46,4044.54 h30
  text "FR-4 High Tg" at 4988.9,3904.21 h30
  text "FR-408" at 4423.46,3895.64 h30
  text "X" at 4835.46,3895.64 h30
  text "OTHER" at 5911.46,3895.64 h30
  text "62 MIL (1.6mm) +/-10%" at 4743.56,3732.92 h30
  text "THICKNESS:" at 4077.23,3728.64 h30
  text "X" at 4615.4,3728.64 h30
  text "OTHER" at 6028.46,3728.64 h30
  text "TOLERANCE:" at 4077.23,3570.64 h30
  text "X" at 4916.53,3570.64 h30
  text "ANSI IPC-6012 TYPE 3 CLASS 2" at 5103.48,3570.64 h30
  text "OTHER +/-" at 5103.46,3414.64 h30
  text "BOW & TWIST:" at 4077.23,3257.64 h30
  text "X" at 4916.53,3257.64 h30
  text "ANSI IPC-6012 TYPE 3 CLASS 2" at 5103.48,3257.64 h30
  text "OTHER +/-" at 5103.46,3099.13 h30
  text "COPPER THICKNESS (FINISHED):" at 4002.46,2963.64 h30
  text "1.4MIL (1oz)" at 4882.46,2810.92 h30
  text "2MIL (1.4oz)" at 5649.46,2810.92 h30
  text "2.8MIL (2oz)" at 6376.46,2810.92 h30
  text "OUTER:" at 4359.46,2806.64 h30
  text "X" at 4754,2806 h30
  text "1.4MIL (1oz)" at 4882.46,2653.92 h30
  text "2.8MIL (2oz)" at 5649.46,2653.92 h30
  text "N/A" at 6376,2654.29 h30
  text "INNER SIGNAL:" at 4070.38,2649.64 h30
  text "X" at 4755.42,2649.64 h30
  text "DRILLING:" at 4002.46,2510.64 h30
  text "REFERENCE:" at 4077.23,2393.64 h30
  text "X" at 4725.46,2393.64 h30
  text "AS SHOWN" at 4912.46,2393.64 h30
  text "X" at 5626.46,2393.64 h30
  text "NC_DRILL FILES" at 5763.46,2393.64 h30
  text "PTH MIN COPPER THICKNESS:" at 4077.23,2235.64 h30
  text "X" at 5427.46,2235.64 h30
  text "1MIL" at 5564.46,2235.64 h30
  text "OTHER" at 6061.46,2235.64 h30
  text "BOARD FINISH:" at 4002.46,2076.64 h30
  text "SILKSCREEN:" at 4157.68,1958.64 h30
  text "X" at 5106.46,1958.64 h30
  text "TOP" at 5232.46,1958.64 h30
  text "X" at 5616.46,1958.64 h30
  text "BOTTOM" at 5743.46,1958.64 h30
  text "SILKSCREEN COLOR:" at 4157.68,1791.64 h30
  text "X" at 5105.42,1791.64 h30
  text "WHITE" at 5232.46,1791.64 h30
  text "OTHER" at 5743.46,1791.64 h30
  text "SOLDER RESIST COLOR:" at 4157.68,1621.64 h30
  text "X" at 4725.42,1462.44 h30
  text "GREEN" at 4852.46,1462.44 h30
  text "BLUE" at 5443.46,1462.44 h30
  text "OTHER" at 5981.46,1462.44 h30
  text "IMMERSION GOLD (ENIG)" at 5063.46,1273.92 h30
  text "ENEPIG" at 6401,1270.64 h30
  text "SURFACE FINISH:" at 4002.46,1269.64 h30
  text "X" at 4876.51,1269.64 h30
  text "IMM. TIN/SILVER OR EQUIV" at 4332,1112.64 h30
  text "OTHER" at 5763.46,1112.64 h30
  text "ARRAY/PANEL:" at 4002.46,933.64 h30
  text "CUT AND TRIM PER MECH LAYER 1" at 5063.46,929.35 h30
  text "N.C. ROUTE" at 5063.46,777.64 h30
  text "X" at 5742.46,777.64 h30
  text "V. SCORE" at 5929.46,777.64 h30
  text "CERTIFICATION:" at 4002.46,640.64 h30
  text "MATERIALS AND WORKMANSHIP FOR ALL PCBS" at 4727.46,640.64 h30
  text "TO MEET OR EXCEED THE REQUIREMENTS OF:" at 4727.46,542.64 h30
  text "X" at 4353.96,406.13 h30
  text "ANSI IPC-A-600F CLASS ->" at 4492.96,406.13 h30
  text "X" at 6132.02,406.13 h30
  text "2" at 6250.96,406.14 h30
  text "1" at 5935.96,404.64 h30
  text "3" at 6604.96,404.64 h30
  text "X" at 4356.02,246.64 h30
  text "UL 94V-0" at 4492.96,246.64 h30
  text "X" at 5168.02,246.64 h30
  text "RoHS" at 5304.96,246.64 h30
  text "OTHER" at 5949.36,246.64 h30
  text "PER ORDER" at 6346.42,246.64 h30
  text "ADDITIONAL REQUIREMENTS:" at 4002.46,105.64 h30
  text "MICROSECTION:" at 4077.23,-9.36 h30
  text "YES" at 4982.96,-9.36 h30
M11 Gerber Information:
  lines w10: -292,-1320.17 6308,-1320.17 ; -292,-1116.83 6310,-1116.83 ; -292,-913.5 -292,-1523.5 3713,-1523.5 6310,-1523.5 6310,-913.5 -291.5,-913.5 -291.5,-1523.5 1284,-1523.5 ; 2173,-1523.5 2173,-913.5 ; 3440,-1116.83 3440,-913.5 ; 4280,-1116.83 4280,-913.5 ; 4902,-1530 4902,-1327.17
  text "ALL ARTWORK VIEWED FROM TOP SIDE" at -228.5,-1045.67 h30
  text "BOARD #:" at 2248,-1045.67 h30
  text ".PRJ_Number" at 2793.5,-1045.67 h30
  text "REV:" at 3638,-1045.67 h30
  text ".PCB_Rev" at 3929.5,-1045.67 h30
  text "SVN REV:" at 4476,-1045.67 h30
  text ".VersionControl_RevNumber" at 4982,-1045.67 h30
  text "LAYER NAME =" at -228.5,-1248.49 h30
  text "PLOT NAME =" at -228.5,-1454.34 h30
  text ".plot_File_Name" at 577,-1454.34 h30
  text "GENERATED    :" at 2250,-1454.34 h30
  text ".Print_Date" at 3119.5,-1454.34 h30
  text ".Print_Time" at 3848.5,-1454.34 h30
  text "TEXAS INSTRUMENTS" at 5113,-1454.34 h30
M12 Stackup:
  lines w6: 11360,7070 13910,7070 ; 11360,7174.4 13910,7174.4 ; 11300,6585 ccw(c11334,6585) 11334,6551 13936,6551 ccw(c13936,6585) 13970,6585 13970,7291 ccw(c13936,7291) 13936,7325 11334,7325 ccw(c11334,7291) 11300,7291 11300,6585
  text "The Stackup Legend below this is static." at 11605.5,7484.5 h30
  text "If you change the stackup, update the Legend." at 11615.5,7394.5 h30
  text "Layer Stack Up Detail for: Ref_Design.PcbDoc" at 11360,7207.1 h30
  text "Layer" at 11360,7135.4 h30
  text "Gerber" at 12255.81,7135.4 h30
  text "Copper" at 12819.33,7135.4 h30
  text "Dielectric" at 13422.04,7135.4 h30
  text "Name" at 11360,7087.4 h30
  text "Document" at 12255.81,7087.4 h30
  text "Thickness" at 12819.33,7087.4 h30
  text "Material" at 13422.04,7087.4 h30
  text "Top Solder Mask" at 11360,6994.44 h30
  text "(.GTS)" at 12255.81,6994.44 h30
  text "Solder Resist" at 13422.04,6994.44 h30
  text "Top Layer" at 11360,6897.69 h30
  text "(.GTL)" at 12255.81,6897.69 h30
  text "1.4mil" at 12819.33,6897.69 h30
  text "FR-4" at 13422.04,6849.31 h30
  text "Bottom Layer" at 11360,6800.94 h30
  text "(.GBL)" at 12255.81,6800.94 h30
  text "1.4mil" at 12819.33,6800.94 h30
  text "Bottom Solder Mask" at 11360,6704.19 h30
  text "(.GBS)" at 12255.81,6704.19 h30
  text "Solder Resist" at 13422.04,6704.19 h30
  text ".Layer_Name" at 577,-1248.49 h30
M13 Component Bodies Top:
  text ".Layer_Name" at 577,-1248.49 h30
M14 Component Bodies Bottom:
  text ".Layer_Name" at 577,-1248.49 h30
M15 Courtyards Top:
  text ".Layer_Name" at 577,-1248.49 h30
M16 Courtyards Bottom:
  text ".Layer_Name" at 577,-1248.49 h30
Drill Drawing:
  text ".Layer_Name" at 577,-1248.49 h30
